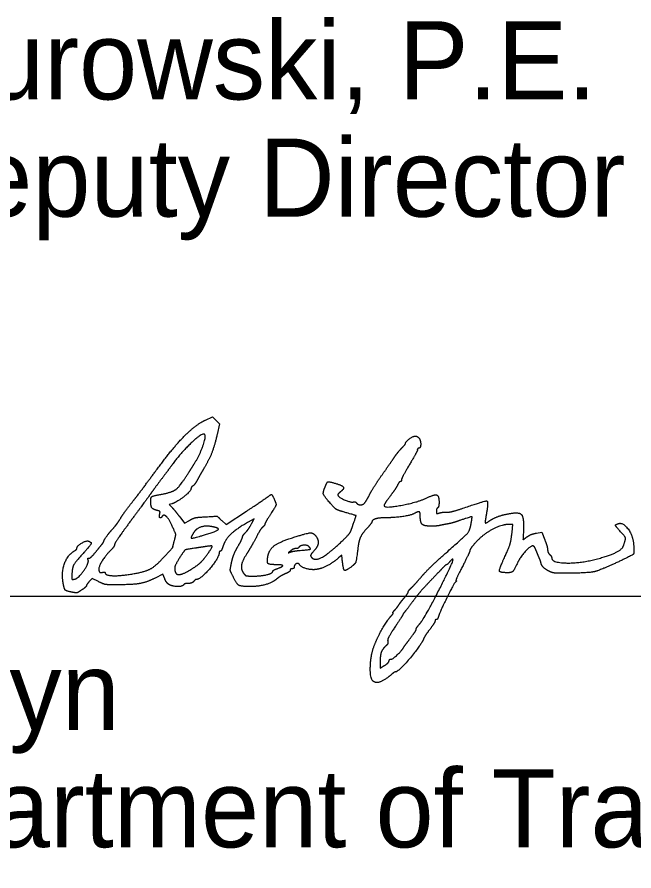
# Model space of a CAD drawing. Extents: x 0 to 36.5, y 0 to 25.3.
# Drawn here: x 25.676 to 26.78, y 7.305 to 8.834 of the extents above; entities that cross this region are included whole.
import ezdxf

# ---------------------------------------------------------------- set-up
doc = ezdxf.new("R2010")
doc.units = 0
doc.layers.add('SH_Data', color=7, linetype='Continuous')
doc.layers.add('SH_Text', color=7, linetype='Continuous')

msp = doc.modelspace()

# ---------------------------------------------------------------- linework, layer by layer
at = {"layer": 'SH_Data'}
msp.add_line((24.5279, 7.7968), (28.0279, 7.7968), dxfattribs=at)
at = {"layer": 'SH_Text'}
for points in [[(26.0131, 8.112), (26.0258, 8.1179), (26.0321, 8.1115), (26.0385, 8.1051), (26.0341, 8.0864)], [(25.9532, 7.962), (25.9482, 7.9605), (25.9534, 7.9553)], [(25.967, 7.9386), (25.9756, 7.9271), (25.9844, 7.9323)], [(26.0422, 7.9323), (26.0503, 7.9247), (26.0866, 7.9488)], [(26.0961, 7.9271), (26.1005, 7.935), (26.095, 7.9321)], [(26.5619, 7.9112), (26.5634, 7.925), (26.5556, 7.925)], [(26.6058, 7.9095), (26.6154, 7.9111), (26.6205, 7.8975)], [(26.2578, 7.8634), (26.2572, 7.8702), (26.2513, 7.8651)], [(25.9402, 7.8278), (25.9369, 7.8358), (25.923, 7.829)], [(25.8216, 7.8227), (25.8101, 7.8285), (25.805, 7.8227)], [(26.3256, 7.6773), (26.3256, 7.6679), (26.3331, 7.6722)]]:
    msp.add_lwpolyline(points, dxfattribs=at)
for points in [[(25.9236, 8.0201), (25.9533, 8.0607), (25.9951, 8.1036), (26.0131, 8.112)], [(26.0117, 8.0862), (26.008, 8.0899), (25.9695, 8.0541), (25.9541, 8.0328)], [(25.9934, 8.0342), (26.0028, 8.049), (26.0148, 8.0831), (26.0117, 8.0862)], [(26.0341, 8.0864), (26.0291, 8.0653), (26.0199, 8.0417), (26.0105, 8.0258)], [(26.3712, 8.0701), (26.3712, 8.0729), (26.3844, 8.0832), (26.3881, 8.0833)], [(26.3881, 8.0833), (26.3901, 8.0833), (26.3931, 8.0821), (26.3947, 8.0805)], [(26.3947, 8.0805), (26.3982, 8.077), (26.3986, 8.0618), (26.3952, 8.0618)], [(26.3508, 8.0448), (26.3547, 8.0506), (26.361, 8.0583), (26.3646, 8.062)], [(26.3646, 8.062), (26.3682, 8.0656), (26.3712, 8.0693), (26.3712, 8.0701)], [(26.3928, 8.0592), (26.3928, 8.0579), (26.3863, 8.0458), (26.3784, 8.0324)], [(26.3952, 8.0618), (26.3939, 8.0618), (26.3928, 8.0606), (26.3928, 8.0592)], [(26.3292, 8.0138), (26.3371, 8.025), (26.3468, 8.0389), (26.3508, 8.0448)], [(25.9541, 8.0328), (25.9505, 8.0279), (25.9411, 8.0152), (25.9332, 8.0047)], [(25.9829, 8.0175), (25.9861, 8.0227), (25.9909, 8.0302), (25.9934, 8.0342)], [(26.3784, 8.0324), (26.3705, 8.019), (26.364, 8.0066), (26.364, 8.0049)], [(25.8834, 7.9667), (25.8923, 7.978), (25.9104, 8.0021), (25.9236, 8.0201)], [(25.9331, 7.9788), (25.9537, 7.9826), (25.9677, 7.9935), (25.9829, 8.0175)], [(26.0105, 8.0258), (26.007, 8.0198), (26.0018, 8.0106), (25.9989, 8.0054)], [(26.3078, 7.9802), (26.3116, 7.9874), (26.3212, 8.0025), (26.3292, 8.0138)], [(25.9332, 8.0047), (25.9253, 7.9942), (25.9172, 7.9832), (25.9152, 7.9803)], [(25.9989, 8.0054), (25.9961, 8.0001), (25.9923, 7.9949), (25.9905, 7.9938)], [(26.2271, 7.992), (26.2309, 8.0011), (26.234, 8.0021), (26.2467, 7.9983)], [(26.2467, 7.9983), (26.2587, 7.9948), (26.2616, 7.9886), (26.2539, 7.9828)], [(26.362, 8.0018), (26.3609, 8.0018), (26.3585, 7.9988), (26.3567, 7.9952)], [(26.364, 8.0049), (26.364, 8.0032), (26.3631, 8.0018), (26.362, 8.0018)], [(25.9872, 7.9884), (25.9872, 7.9847), (25.9614, 7.9646), (25.9532, 7.962)], [(25.9905, 7.9938), (25.9887, 7.9928), (25.9872, 7.9904), (25.9872, 7.9884)], [(26.2369, 7.9626), (26.2254, 7.9757), (26.2232, 7.9824), (26.2271, 7.992)], [(26.2539, 7.9828), (26.2512, 7.9807), (26.2497, 7.9778), (26.2506, 7.9765)], [(26.3567, 7.9952), (26.3549, 7.9915), (26.3488, 7.9824), (26.3431, 7.975)], [(25.8619, 7.9373), (25.8648, 7.9421), (25.8745, 7.9553), (25.8834, 7.9667)], [(25.9152, 7.9803), (25.9132, 7.9773), (25.8978, 7.9564), (25.881, 7.9337)], [(25.9152, 7.9667), (25.9152, 7.9736), (25.9193, 7.9764), (25.9331, 7.9788)], [(25.9262, 7.9503), (25.919, 7.9521), (25.9152, 7.9578), (25.9152, 7.9667)], [(26.0866, 7.9488), (26.1065, 7.9621), (26.1241, 7.974), (26.1257, 7.9753)], [(26.1257, 7.9753), (26.1302, 7.9791), (26.1326, 7.9782), (26.1356, 7.9716)], [(26.1356, 7.9716), (26.14, 7.962), (26.139, 7.9579), (26.1288, 7.942)], [(26.2506, 7.9765), (26.2533, 7.9727), (26.2732, 7.9645), (26.2778, 7.9653)], [(26.2985, 7.964), (26.2998, 7.9656), (26.304, 7.9729), (26.3078, 7.9802)], [(26.3431, 7.975), (26.3374, 7.9675), (26.3328, 7.9602), (26.3328, 7.9589)], [(26.3328, 7.9589), (26.3328, 7.9536), (26.3924, 7.9646), (26.4104, 7.9731)], [(26.4104, 7.9731), (26.4233, 7.9793), (26.4312, 7.9762), (26.4312, 7.9648)], [(26.4735, 7.954), (26.5139, 7.9679), (26.5198, 7.9663), (26.5157, 7.9424)], [(25.9534, 7.9553), (25.9562, 7.9525), (25.9623, 7.945), (25.967, 7.9386)], [(26.2604, 7.9474), (26.2496, 7.9506), (26.2447, 7.9537), (26.2369, 7.9626)], [(26.2778, 7.9653), (26.2801, 7.9657), (26.2827, 7.9649), (26.2835, 7.9635)], [(26.2835, 7.9635), (26.2857, 7.96), (26.2957, 7.9603), (26.2985, 7.964)], [(26.4288, 7.955), (26.4275, 7.9541), (26.4264, 7.9513), (26.4264, 7.9487)], [(26.4312, 7.9648), (26.4312, 7.9602), (26.4301, 7.9558), (26.4288, 7.955)], [(26.4447, 7.947), (26.4489, 7.9468), (26.4618, 7.95), (26.4735, 7.954)], [(25.8456, 7.9154), (25.8522, 7.9228), (25.8564, 7.9285), (25.8619, 7.9373)], [(25.9313, 7.9441), (25.9322, 7.9476), (25.9309, 7.9491), (25.9262, 7.9503)], [(25.9355, 7.9393), (25.9331, 7.9354), (25.9299, 7.9389), (25.9313, 7.9441)], [(25.9543, 7.9207), (25.9482, 7.9344), (25.9385, 7.944), (25.9355, 7.9393)], [(25.9844, 7.9323), (25.9909, 7.9362), (25.9985, 7.9379), (26.0136, 7.9388)], [(26.0136, 7.9388), (26.0339, 7.94), (26.0341, 7.9399), (26.0422, 7.9323)], [(26.1288, 7.942), (26.1235, 7.9339), (26.1192, 7.9263), (26.1192, 7.9252)], [(26.2772, 7.9237), (26.2828, 7.9405), (26.2825, 7.9411), (26.2604, 7.9474)], [(26.3354, 7.937), (26.3239, 7.937), (26.3112, 7.9332), (26.3112, 7.9298)], [(26.3861, 7.9443), (26.3806, 7.9413), (26.3504, 7.937), (26.3354, 7.937)], [(26.3976, 7.9396), (26.3976, 7.9469), (26.3939, 7.9485), (26.3861, 7.9443)], [(26.4169, 7.922), (26.4045, 7.922), (26.3976, 7.9283), (26.3976, 7.9396)], [(26.4264, 7.9487), (26.4264, 7.9447), (26.4274, 7.9442), (26.4318, 7.9456)], [(26.4318, 7.9456), (26.4348, 7.9465), (26.4406, 7.9472), (26.4447, 7.947)], [(26.4888, 7.9274), (26.4909, 7.9389), (26.4891, 7.9393), (26.4682, 7.9321)], [(26.5157, 7.9424), (26.5143, 7.9348), (26.5136, 7.9282), (26.5141, 7.9277)], [(26.5216, 7.9316), (26.5289, 7.9366), (26.5471, 7.9429), (26.5608, 7.9451)], [(26.5608, 7.9451), (26.5754, 7.9474), (26.5831, 7.937), (26.5823, 7.9157)], [(25.881, 7.9337), (25.8643, 7.9111), (25.8505, 7.8909), (25.8504, 7.889)], [(26.0254, 7.921), (26.0145, 7.9232), (25.9971, 7.9181), (25.9928, 7.9115)], [(26.0148, 7.9075), (26.034, 7.9134), (26.038, 7.9185), (26.0254, 7.921)], [(26.095, 7.9321), (26.0716, 7.9195), (26.0488, 7.8989), (26.0447, 7.8864)], [(26.0833, 7.9089), (26.0887, 7.9149), (26.0912, 7.9185), (26.0961, 7.9271)], [(26.1192, 7.9252), (26.1192, 7.9241), (26.1176, 7.9218), (26.1156, 7.9202)], [(26.2589, 7.8964), (26.2693, 7.9064), (26.2734, 7.9126), (26.2772, 7.9237)], [(26.3112, 7.9298), (26.3112, 7.9289), (26.307, 7.9235), (26.3018, 7.9177)], [(26.4336, 7.9234), (26.4303, 7.9226), (26.4228, 7.922), (26.4169, 7.922)], [(26.4468, 7.926), (26.4428, 7.9253), (26.4369, 7.9242), (26.4336, 7.9234)], [(26.4439, 7.8744), (26.4795, 7.906), (26.4864, 7.9142), (26.4888, 7.9274)], [(26.4682, 7.9321), (26.4604, 7.9294), (26.4507, 7.9266), (26.4468, 7.926)], [(26.5556, 7.925), (26.5429, 7.925), (26.5091, 7.9065), (26.4969, 7.893)], [(26.5141, 7.9277), (26.5145, 7.9272), (26.5179, 7.929), (26.5216, 7.9316)], [(26.7524, 7.9163), (26.7471, 7.922), (26.7468, 7.9247), (26.7515, 7.9264)], [(26.7515, 7.9264), (26.76, 7.9297), (26.7785, 7.9048), (26.7795, 7.8885)], [(25.8312, 7.895), (25.8312, 7.8966), (25.8403, 7.9096), (25.8456, 7.9154)], [(25.9576, 7.8962), (25.9602, 7.906), (25.9599, 7.9082), (25.9543, 7.9207)], [(25.9928, 7.9115), (25.9858, 7.9008), (25.9903, 7.9), (26.0148, 7.9075)], [(26.0793, 7.9019), (26.0796, 7.9037), (26.0813, 7.9068), (26.0833, 7.9089)], [(26.1087, 7.9109), (26.1006, 7.8955), (26.0928, 7.8817), (26.0867, 7.872)], [(26.1156, 7.9202), (26.1137, 7.9186), (26.1106, 7.9144), (26.1087, 7.9109)], [(26.1626, 7.8992), (26.1944, 7.9098), (26.2078, 7.9102), (26.2129, 7.9008)], [(26.3018, 7.9177), (26.2933, 7.9083), (26.2876, 7.8957), (26.286, 7.883)], [(26.5472, 7.8633), (26.5563, 7.8832), (26.5603, 7.8964), (26.5619, 7.9112)], [(26.5823, 7.9157), (26.5816, 7.8973), (26.5815, 7.8976), (26.5892, 7.9031)], [(26.5892, 7.9031), (26.593, 7.9058), (26.6004, 7.9087), (26.6058, 7.9095)], [(26.7615, 7.8872), (26.7655, 7.899), (26.7639, 7.9039), (26.7524, 7.9163)], [(25.7832, 7.8829), (25.7833, 7.8867), (25.8, 7.8967), (25.8038, 7.8952)], [(25.8038, 7.8952), (25.8098, 7.8929), (25.8075, 7.888), (25.7932, 7.8721)], [(25.8167, 7.8758), (25.822, 7.8824), (25.8275, 7.8891), (25.8288, 7.8907)], [(25.8288, 7.8907), (25.8301, 7.8923), (25.8312, 7.8942), (25.8312, 7.895)], [(25.938, 7.8657), (25.9541, 7.8832), (25.9544, 7.8838), (25.9576, 7.8962)], [(26.0708, 7.8848), (26.0752, 7.8925), (26.079, 7.9002), (26.0793, 7.9019)], [(26.1249, 7.8681), (26.1271, 7.8794), (26.1433, 7.8928), (26.1626, 7.8992)], [(26.2019, 7.8675), (26.2072, 7.8589), (26.2339, 7.8724), (26.2589, 7.8964)], [(26.2129, 7.9008), (26.2161, 7.8947), (26.2127, 7.8833), (26.2053, 7.8754)], [(26.4969, 7.893), (26.4911, 7.8865), (26.4864, 7.88), (26.4864, 7.8784)], [(26.6205, 7.8975), (26.6233, 7.8901), (26.6256, 7.8819), (26.6256, 7.8794)], [(25.7583, 7.8213), (25.7554, 7.8398), (25.7661, 7.8699), (25.7785, 7.8776)], [(25.7785, 7.8776), (25.7811, 7.8792), (25.7832, 7.8816), (25.7832, 7.8829)], [(25.8044, 7.8645), (25.8058, 7.8641), (25.8113, 7.8692), (25.8167, 7.8758)], [(25.843, 7.8782), (25.8332, 7.8686), (25.8208, 7.8465), (25.8226, 7.8418)], [(25.8504, 7.889), (25.8503, 7.887), (25.847, 7.8822), (25.843, 7.8782)], [(25.9956, 7.8827), (25.9778, 7.8801), (25.9758, 7.879), (25.9685, 7.8678)], [(26.013, 7.8854), (26.0074, 7.8845), (25.9995, 7.8833), (25.9956, 7.8827)], [(26.018, 7.8737), (26.0258, 7.8851), (26.0249, 7.8872), (26.013, 7.8854)], [(26.0396, 7.877), (26.0385, 7.877), (26.0376, 7.8756), (26.0375, 7.874)], [(26.0447, 7.8864), (26.043, 7.8812), (26.0407, 7.877), (26.0396, 7.877)], [(26.0599, 7.857), (26.0615, 7.8647), (26.0664, 7.8772), (26.0708, 7.8848)], [(26.1658, 7.878), (26.1612, 7.8742), (26.1612, 7.8742), (26.166, 7.8759)], [(26.1747, 7.8818), (26.1724, 7.8818), (26.1684, 7.88), (26.1658, 7.878)], [(26.166, 7.8759), (26.1686, 7.8768), (26.1762, 7.878), (26.1828, 7.8786)], [(26.1802, 7.8839), (26.1795, 7.8827), (26.177, 7.8818), (26.1747, 7.8818)], [(26.1987, 7.885), (26.1959, 7.8884), (26.1825, 7.8876), (26.1802, 7.8839)], [(26.1828, 7.8786), (26.1995, 7.8801), (26.2019, 7.8811), (26.1987, 7.885)], [(26.2053, 7.8754), (26.2025, 7.8725), (26.201, 7.869), (26.2019, 7.8675)], [(26.286, 7.883), (26.2832, 7.8605), (26.2814, 7.855), (26.2758, 7.8505)], [(26.4864, 7.8784), (26.4864, 7.8768), (26.4804, 7.864), (26.4732, 7.8498)], [(26.5988, 7.8866), (26.5945, 7.8866), (26.5762, 7.8661), (26.5715, 7.8559)], [(26.6044, 7.88), (26.6029, 7.8836), (26.6004, 7.8866), (26.5988, 7.8866)], [(26.6103, 7.8658), (26.6085, 7.87), (26.6058, 7.8763), (26.6044, 7.88)], [(26.6256, 7.8794), (26.6256, 7.8769), (26.6272, 7.8733), (26.6292, 7.8713)], [(26.7126, 7.863), (26.7363, 7.8692), (26.7593, 7.8806), (26.7615, 7.8872)], [(26.7795, 7.8885), (26.7804, 7.8732), (26.7778, 7.8701), (26.7544, 7.8591)], [(25.7932, 7.8721), (25.7795, 7.857), (25.7745, 7.8468), (25.7739, 7.833)], [(25.7787, 7.827), (25.7851, 7.8279), (25.8052, 7.8564), (25.8032, 7.8616)], [(25.8032, 7.8616), (25.8024, 7.8635), (25.803, 7.8648), (25.8044, 7.8645)], [(25.8815, 7.8363), (25.9042, 7.84), (25.9238, 7.8502), (25.938, 7.8657)], [(25.9685, 7.8678), (25.9603, 7.8551), (25.9571, 7.8453), (25.9593, 7.8395)], [(25.9881, 7.845), (25.9993, 7.852), (26.0102, 7.8626), (26.018, 7.8737)], [(26.0375, 7.874), (26.0374, 7.8654), (26.0043, 7.8266), (25.9972, 7.8266)], [(26.0867, 7.872), (26.0787, 7.8594), (26.0765, 7.8442), (26.0816, 7.8374)], [(26.1385, 7.853), (26.127, 7.853), (26.1229, 7.8575), (26.1249, 7.8681)], [(26.2513, 7.8651), (26.2419, 7.8569), (26.2219, 7.8463), (26.2128, 7.8446)], [(26.2758, 7.8505), (26.264, 7.8413), (26.2597, 7.8444), (26.2578, 7.8634)], [(26.3973, 7.7479), (26.4049, 7.7566), (26.4582, 7.8604), (26.4561, 7.8624)], [(26.3999, 7.8317), (26.4071, 7.8401), (26.4269, 7.8593), (26.4439, 7.8744)], [(26.4561, 7.8624), (26.4554, 7.8632), (26.4528, 7.8613), (26.4504, 7.8584)], [(26.5546, 7.8386), (26.5401, 7.8386), (26.5385, 7.844), (26.5472, 7.8633)], [(26.6137, 7.8562), (26.6136, 7.8573), (26.6121, 7.8616), (26.6103, 7.8658)], [(26.6292, 7.8713), (26.6312, 7.8693), (26.6328, 7.8666), (26.6328, 7.8653)], [(26.6328, 7.8653), (26.6328, 7.8568), (26.6834, 7.8553), (26.7126, 7.863)], [(25.9593, 7.8395), (25.9614, 7.8342), (25.9749, 7.8369), (25.9881, 7.845)], [(26.0619, 7.833), (26.0575, 7.8421), (26.0573, 7.8443), (26.0599, 7.857)], [(26.1336, 7.8412), (26.1336, 7.8422), (26.1373, 7.8444), (26.1419, 7.846)], [(26.1419, 7.846), (26.1522, 7.8498), (26.1506, 7.853), (26.1385, 7.853)], [(26.1684, 7.8458), (26.1664, 7.8458), (26.1648, 7.8447), (26.1648, 7.8433)], [(26.172, 7.8491), (26.172, 7.8473), (26.1704, 7.8458), (26.1684, 7.8458)], [(26.1815, 7.8531), (26.1795, 7.8564), (26.172, 7.8532), (26.172, 7.8491)], [(26.2128, 7.8446), (26.2042, 7.8431), (26.1844, 7.8484), (26.1815, 7.8531)], [(26.4358, 7.8452), (26.4317, 7.8409), (26.4212, 7.8298), (26.4124, 7.8205)], [(26.4446, 7.853), (26.4438, 7.853), (26.4399, 7.8494), (26.4358, 7.8452)], [(26.4504, 7.8584), (26.448, 7.8554), (26.4454, 7.853), (26.4446, 7.853)], [(26.4732, 7.8498), (26.4659, 7.8357), (26.4607, 7.8241), (26.4618, 7.8241)], [(26.5715, 7.8559), (26.5658, 7.8435), (26.5609, 7.8386), (26.5546, 7.8386)], [(26.6293, 7.8406), (26.6223, 7.844), (26.6138, 7.8524), (26.6137, 7.8562)], [(26.7544, 7.8591), (26.7196, 7.8428), (26.6985, 7.838), (26.6592, 7.8376)], [(25.7739, 7.833), (25.7737, 7.8274), (25.7745, 7.8264), (25.7787, 7.827)], [(25.8226, 7.8418), (25.8235, 7.8394), (25.8258, 7.8385), (25.8288, 7.8393)], [(25.8288, 7.8393), (25.8314, 7.8399), (25.8336, 7.8396), (25.8336, 7.8385)], [(25.8336, 7.8385), (25.8336, 7.8339), (25.8592, 7.8327), (25.8815, 7.8363)], [(26.0937, 7.8138), (26.0762, 7.8139), (26.0692, 7.8182), (26.0619, 7.833)], [(26.0816, 7.8374), (26.0844, 7.8336), (26.088, 7.8326), (26.0992, 7.8326)], [(26.0992, 7.8326), (26.1132, 7.8326), (26.1336, 7.8377), (26.1336, 7.8412)], [(26.1594, 7.8384), (26.152, 7.8351), (26.1444, 7.8306), (26.1402, 7.8271)], [(26.1648, 7.8433), (26.1648, 7.8419), (26.1624, 7.8397), (26.1594, 7.8384)], [(26.3814, 7.8113), (26.3844, 7.8141), (26.3927, 7.8233), (26.3999, 7.8317)], [(26.6592, 7.8376), (26.6442, 7.8374), (26.6339, 7.8385), (26.6293, 7.8406)], [(25.7749, 7.8036), (25.764, 7.8056), (25.7602, 7.8097), (25.7583, 7.8213)], [(25.8, 7.8151), (25.8, 7.8142), (25.7962, 7.8108), (25.7916, 7.8077)], [(25.805, 7.8227), (25.8022, 7.8195), (25.8, 7.8161), (25.8, 7.8151)], [(25.8524, 7.817), (25.8368, 7.817), (25.8309, 7.8181), (25.8216, 7.8227)], [(25.923, 7.829), (25.9074, 7.8212), (25.8823, 7.817), (25.8524, 7.817)], [(25.9484, 7.8172), (25.9458, 7.8186), (25.9421, 7.8234), (25.9402, 7.8278)], [(25.974, 7.817), (25.972, 7.8138), (25.9545, 7.8139), (25.9484, 7.8172)], [(25.9822, 7.8194), (25.9785, 7.8194), (25.9748, 7.8183), (25.974, 7.817)], [(25.992, 7.823), (25.9903, 7.821), (25.9859, 7.8194), (25.9822, 7.8194)], [(25.9972, 7.8266), (25.996, 7.8266), (25.9936, 7.8249), (25.992, 7.823)], [(26.1402, 7.8271), (26.1325, 7.8207), (26.1082, 7.8138), (26.0937, 7.8138)], [(26.4124, 7.8205), (26.4036, 7.8113), (26.3937, 7.8), (26.3904, 7.7955)], [(26.461, 7.8223), (26.4583, 7.8205), (26.4331, 7.7695), (26.4301, 7.76)], [(26.4618, 7.8241), (26.4628, 7.8241), (26.4624, 7.8233), (26.461, 7.8223)], [(25.7916, 7.8077), (25.7851, 7.8032), (25.7815, 7.8023), (25.7749, 7.8036)], [(26.3694, 7.7943), (26.373, 7.7985), (26.376, 7.8029), (26.376, 7.8041)], [(26.376, 7.8041), (26.376, 7.8052), (26.3785, 7.8085), (26.3814, 7.8113)], [(26.3592, 7.7809), (26.3612, 7.784), (26.3658, 7.79), (26.3694, 7.7943)], [(26.3904, 7.7955), (26.3823, 7.7846), (26.3718, 7.7708), (26.3688, 7.7673)], [(26.3488, 7.7666), (26.3479, 7.7666), (26.3491, 7.7685), (26.3514, 7.771)], [(26.3514, 7.771), (26.3537, 7.7734), (26.3572, 7.7779), (26.3592, 7.7809)], [(26.3154, 7.7086), (26.3213, 7.7234), (26.3384, 7.7533), (26.3455, 7.7612)], [(26.3455, 7.7612), (26.3482, 7.7641), (26.3497, 7.7666), (26.3488, 7.7666)], [(26.3664, 7.7634), (26.3664, 7.7628), (26.36, 7.7529), (26.3523, 7.7413)], [(26.3688, 7.7673), (26.3675, 7.7657), (26.3664, 7.7639), (26.3664, 7.7634)], [(26.4262, 7.7546), (26.425, 7.7546), (26.424, 7.7534), (26.424, 7.7521)], [(26.4301, 7.76), (26.4292, 7.757), (26.4274, 7.7546), (26.4262, 7.7546)], [(26.3523, 7.7413), (26.3436, 7.7282), (26.3387, 7.7185), (26.3394, 7.7158)], [(26.3802, 7.7217), (26.3858, 7.7291), (26.3904, 7.7362), (26.3904, 7.7376)], [(26.3904, 7.7376), (26.3904, 7.7389), (26.3935, 7.7435), (26.3973, 7.7479)], [(26.424, 7.7521), (26.424, 7.7507), (26.4197, 7.7439), (26.4145, 7.737)], [(26.4145, 7.737), (26.4093, 7.7301), (26.4042, 7.7221), (26.4031, 7.7193)], [(26.3136, 7.6441), (26.3076, 7.6479), (26.3089, 7.6922), (26.3154, 7.7086)], [(26.3357, 7.7072), (26.3298, 7.7019), (26.3256, 7.6896), (26.3256, 7.6773)], [(26.3394, 7.7158), (26.34, 7.7132), (26.3385, 7.7096), (26.3357, 7.7072)], [(26.4031, 7.7193), (26.3994, 7.7094), (26.3583, 7.661), (26.3536, 7.661)], [(26.3676, 7.7045), (26.3689, 7.7066), (26.3746, 7.7144), (26.3802, 7.7217)], [(26.3448, 7.6838), (26.3467, 7.6826), (26.3633, 7.6977), (26.3676, 7.7045)], [(26.3331, 7.6722), (26.3373, 7.6746), (26.3412, 7.6784), (26.3418, 7.6807)], [(26.3418, 7.6807), (26.3424, 7.683), (26.3438, 7.6844), (26.3448, 7.6838)], [(26.3536, 7.661), (26.3522, 7.661), (26.3489, 7.6589), (26.3461, 7.6564)], [(26.3461, 7.6564), (26.3399, 7.6507), (26.324, 7.6417), (26.3201, 7.6418)], [(26.3201, 7.6418), (26.3185, 7.6418), (26.3156, 7.6429), (26.3136, 7.6441)]]:
    msp.add_open_spline(points, degree=2, dxfattribs=at)

# ---------------------------------------------------------------- texts
for s, p in [('Anthony C. Turowski, P.E.', (24.5279, 8.6862)), ('District       Deputy Director', (24.5279, 8.4762)), ('Pamela Boratyn', (24.5279, 7.5568)), ('Director, Department of Transportation', (24.5279, 7.3468))]:
    msp.add_text(s, height=0.14, dxfattribs=at).set_placement(p)

doc.saveas('drawing.dxf')
